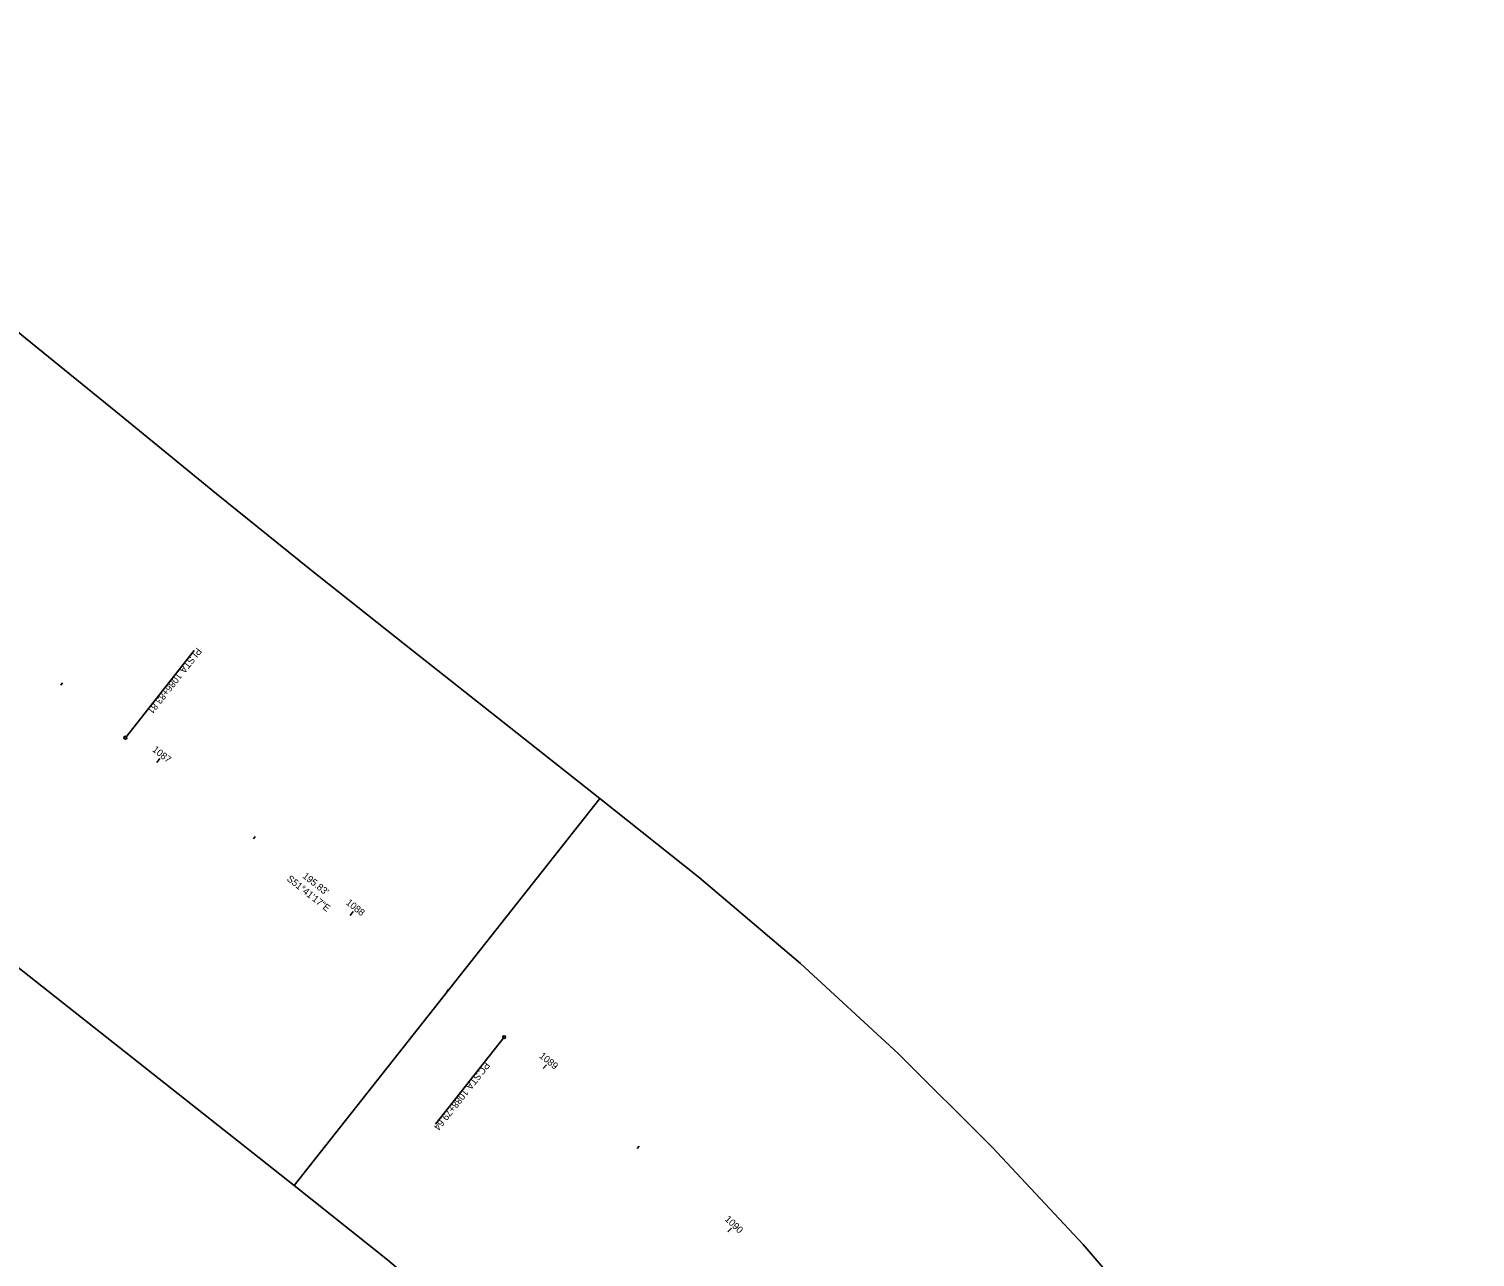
# Model space of a CAD drawing. Extents: x 1846275 to 1850613, y 577927 to 582526.
# Drawn here: x 1849961 to 1850548, y 578403 to 578901 of the extents above; entities that cross this region are included whole.
import ezdxf

# ---------------------------------------------------------------- set-up
doc = ezdxf.new("R2010")
doc.units = 0
for name, color, linetype in [('GE_P_Alignment_100_Cardinal_Points', 7, 'Continuous'), ('PM_P_Cells', 7, 'Continuous'), ('PM_P_Stop_Line', 7, 'Continuous'), ('SH_Named_Boundary', 7, 'Continuous'), ('XS_P_Pavt_Surface', 7, 'Continuous')]:
    doc.layers.add(name, color=color, linetype=linetype)

msp = doc.modelspace()

# ---------------------------------------------------------------- linework, layer by layer
at = {"layer": 'GE_P_Alignment_100_Cardinal_Points'}
for p, q in [((1849974.15, 578634.63), (1849974.9, 578635.56)), ((1850013.05, 578603.22), (1850014.29, 578604.79)), ((1850052.28, 578572.22), (1850053.02, 578573.16)), ((1850091.51, 578541.22), (1850092.75, 578542.79)), ((1850130.74, 578510.22), (1850131.49, 578511.17)), ((1850169.87, 578479.1), (1850171.14, 578480.65)), ((1850207.98, 578446.73), (1850208.78, 578447.63)), ((1850244.79, 578412.9), (1850246.17, 578414.35))]:
    msp.add_line(p, q, dxfattribs=at)
at = {"layer": 'PM_P_Cells'}
for p, q in [((1850000.34, 578613.25), (1850028.24, 578648.56)), ((1850154, 578491.85), (1850126.1, 578456.54))]:
    msp.add_line(p, q, dxfattribs=at)
for centre in [(1850000.34, 578613.25), (1850154, 578491.85)]:
    msp.add_circle(centre, 0.6, dxfattribs=at)
at = {"layer": 'SH_Named_Boundary'}
for points in [[(1849808.1, 578900.63), (1849676.85, 578749.73), (1849716.51, 578715.95), (1849755.98, 578683.57), (1849794.72, 578651.96), (1849833.46, 578620.35), (1849872.2, 578588.74), (1849910.94, 578557.13), (1849951.07, 578524.74), (1849990.3, 578493.74), (1850029.53, 578462.75), (1850068.76, 578431.75), (1850192.75, 578588.68), (1850153.52, 578619.68), (1850114.29, 578650.67), (1850075.05, 578681.67), (1850037.38, 578712.1), (1849998.64, 578743.71), (1849959.9, 578775.32), (1849921.16, 578806.93), (1849882.41, 578838.54), (1849844.57, 578869.58)], [(1850192.75, 578588.68), (1850068.76, 578431.75), (1850106.65, 578401.62), (1850141.78, 578371.79), (1850175.71, 578340.6), (1850208.4, 578308.11), (1850239.8, 578274.37), (1850269.85, 578239.42), (1850298.51, 578203.33), (1850325.74, 578166.15), (1850351.5, 578127.93), (1850375.74, 578088.74), (1850547.86, 578190.59), (1850519.5, 578236.44), (1850489.38, 578281.14), (1850457.53, 578324.63), (1850424, 578366.85), (1850388.85, 578407.72), (1850352.13, 578447.18), (1850313.9, 578485.18), (1850274.21, 578521.66), (1850233.13, 578556.56)]]:
    msp.add_lwpolyline(points, close=True, dxfattribs=at)

# ---------------------------------------------------------------- texts
at = {"layer": 'GE_P_Alignment_100_Cardinal_Points'}
for s, rotation, p in [('1087', 321.68813, (1850011.04, 578607.99)), ('1088', 321.68813, (1850089.57, 578545.94)), ('1089', 320.776, (1850168.02, 578483.84)), ('1090', 316.29643, (1850243.29, 578417.8))]:
    msp.add_text(s, height=2.8, rotation=rotation, dxfattribs=at).set_placement(p)
at = {"layer": 'PM_P_Cells'}
for s, p in [('PI', (1850029.4, 578649.96)), (' STA. ', (1850027.29, 578647.3)), ('1086+83.81', (1850021.44, 578639.88)), ('PC', (1850146.3, 578482.04)), (' STA. ', (1850143.46, 578478.45)), ('1088+79.64', (1850137.6, 578471.03))]:
    msp.add_text(s, height=2.8, rotation=231.68813, dxfattribs=at).set_placement(p)
at = {"layer": 'PM_P_Stop_Line'}
msp.add_text('S51°41\'17"E', height=2.8, rotation=321.68813, dxfattribs=at).set_placement((1850065.61, 578555.57))
at = {"layer": 'XS_P_Pavt_Surface'}
msp.add_text("195.83'", height=2.8, rotation=321.68813, dxfattribs=at).set_placement((1850071.96, 578556.73))

doc.saveas('drawing.dxf')
